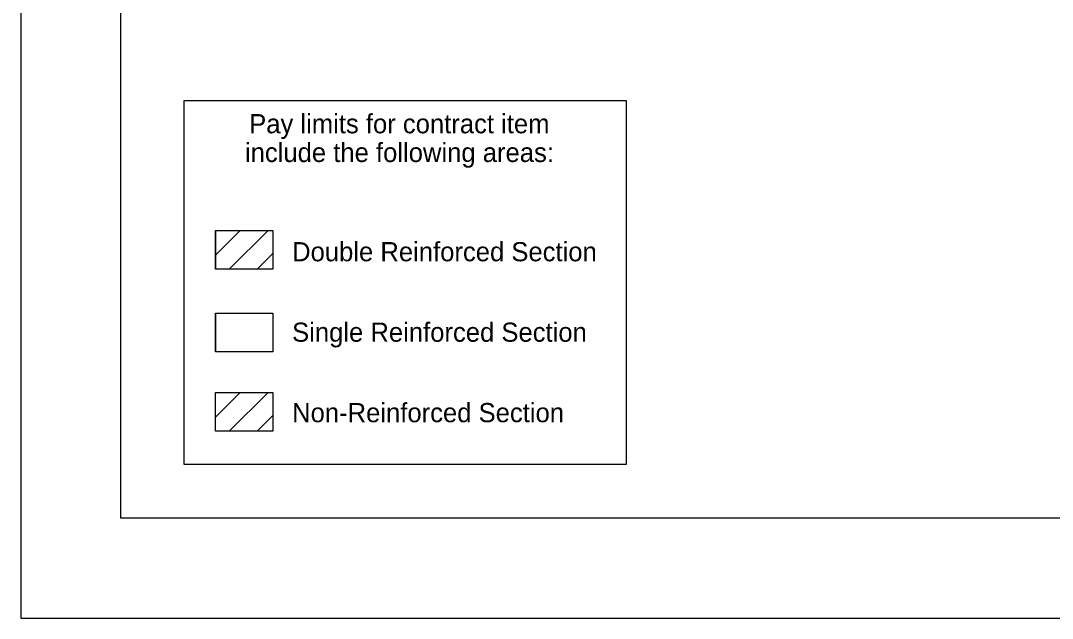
# Model space of a CAD drawing. Extents: x -2135039 to -2131695, y -2139150 to -2136566.
# Drawn here: x -2135039 to -2133962, y -2139150 to -2138527 of the extents above; entities that cross this region are included whole.
import ezdxf

# ---------------------------------------------------------------- set-up
doc = ezdxf.new("R2010")
doc.units = 0
for name, color, linetype in [('dsnDOTLogo', 7, 'Continuous'), ('Level 1', 7, 'Continuous'), ('Level 2', 7, 'Continuous'), ('Level 3', 7, 'Continuous')]:
    doc.layers.add(name, color=color, linetype=linetype)

msp = doc.modelspace()

# ---------------------------------------------------------------- linework, layer by layer
at = {"layer": 'dsnDOTLogo'}
msp.add_lwpolyline([(-2135038.9, -2139150.4), (-2131694.9, -2139150.4), (-2131694.9, -2136566.4), (-2135038.9, -2136566.4)], close=True, dxfattribs=at)
at = {"layer": 'Level 1'}
msp.add_lwpolyline([(-2134934.4, -2137035.9), (-2131799.4, -2137035.9), (-2131799.4, -2139045.9), (-2134934.4, -2139045.9)], close=True, dxfattribs=at)
at = {"layer": 'Level 2'}
for p, q in [((-2134835.3, -2138745.7), (-2134775.6, -2138745.7)), ((-2134835.3, -2138745.7), (-2134835.3, -2138786.1)), ((-2134835.3, -2138771.3), (-2134809.7, -2138745.7)), ((-2134821.1, -2138786.1), (-2134780.6, -2138745.7)), ((-2134775.6, -2138745.7), (-2134775.6, -2138786.1)), ((-2134792, -2138786.1), (-2134775.6, -2138769.7)), ((-2134775.6, -2138786.1), (-2134835.3, -2138786.1)), ((-2134835.3, -2138831.7), (-2134775.6, -2138831.7)), ((-2134835.3, -2138831.7), (-2134835.3, -2138872.2)), ((-2134775.6, -2138831.7), (-2134775.6, -2138872.2)), ((-2134775.6, -2138872.2), (-2134835.3, -2138872.2)), ((-2134835.3, -2138940.3), (-2134809.7, -2138914.7)), ((-2134821.1, -2138955.2), (-2134780.6, -2138914.7)), ((-2134792, -2138955.2), (-2134775.6, -2138938.8))]:
    msp.add_line(p, q, dxfattribs=at)
for points in [[(-2134868.1, -2138609.7), (-2134406.8, -2138609.7), (-2134406.8, -2138989.9), (-2134868.1, -2138989.9)], [(-2134835.3, -2138914.7), (-2134775.6, -2138914.7), (-2134775.6, -2138955.2), (-2134835.3, -2138955.2)]]:
    msp.add_lwpolyline(points, close=True, dxfattribs=at)
at = {"layer": 'Level 3'}
for p, q in [((-2134835.3, -2138745.7), (-2134775.6, -2138745.7)), ((-2134835.3, -2138786.1), (-2134835.3, -2138745.7)), ((-2134775.6, -2138745.7), (-2134775.6, -2138786.1)), ((-2134775.6, -2138786.1), (-2134835.3, -2138786.1)), ((-2134835.3, -2138831.7), (-2134775.6, -2138831.7)), ((-2134835.3, -2138872.2), (-2134835.3, -2138831.7)), ((-2134775.6, -2138831.7), (-2134775.6, -2138872.2)), ((-2134775.6, -2138872.2), (-2134835.3, -2138872.2))]:
    msp.add_line(p, q, dxfattribs=at)

# ---------------------------------------------------------------- texts
for s, p in [('Pay limits for contract item', (-2134800.3, -2138644.1)), ('include the following areas:', (-2134804.7, -2138674.1)), ('Double Reinforced Section', (-2134755.5, -2138777.7)), ('Single Reinforced Section', (-2134755.5, -2138861.7)), ('Non-Reinforced Section', (-2134755.5, -2138945.7))]:
    msp.add_text(s, height=20, dxfattribs=at).set_placement(p)

doc.saveas('drawing.dxf')
